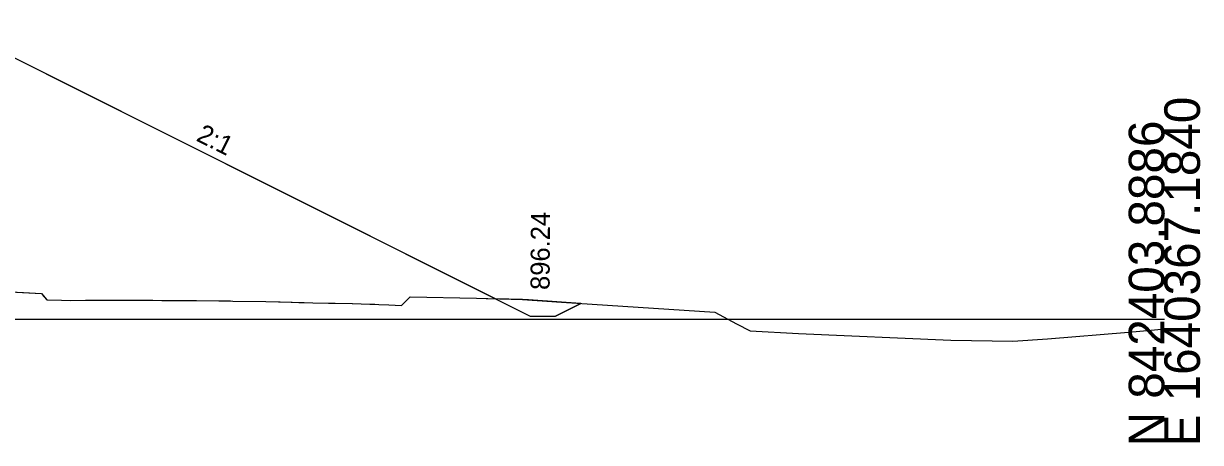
# Model space of a CAD drawing. Extents: x -26 to 1638757, y -10 to 843341.
# Drawn here: x 1260.3 to 1352.8, y 1490.3 to 1523.2 of the extents above; entities that cross this region are included whole.
import ezdxf

# ---------------------------------------------------------------- set-up
doc = ezdxf.new("R2010")
doc.units = 0
for name, color, linetype in [('Exist Cross Section Cell', 7, 'Continuous'), ('Exist XS Ground Line', 7, 'Continuous'), ('Prop CMT Slope Grass', 7, 'Continuous'), ('Prop XS DDE', 7, 'Continuous'), ('Prop XS SE Text', 7, 'Continuous'), ('Prop XS Side Slope Text', 7, 'Continuous'), ('Scratch_Level_0', 7, 'Continuous'), ('Scratch_Level_2', 7, 'Continuous'), ('Scratch_Level_3', 7, 'Continuous')]:
    doc.layers.add(name, color=color, linetype=linetype)

msp = doc.modelspace()

# ---------------------------------------------------------------- linework, layer by layer
at = {"layer": 'Exist Cross Section Cell'}
msp.add_line((1150, 1500), (1350, 1500), dxfattribs=at)
at = {"layer": 'Exist XS Ground Line'}
for points in [[(1257.864, 1502.232), (1261.7, 1502.007), (1261.875, 1501.79), (1262.103, 1501.511), (1263.28, 1501.48), (1263.993, 1501.461), (1265.156, 1501.482), (1265.721, 1501.488), (1266.927, 1501.495), (1268.445, 1501.501), (1270.439, 1501.483), (1271.168, 1501.477), (1271.724, 1501.472), (1273.892, 1501.46), (1275.651, 1501.437), (1276.088, 1501.432), (1276.57, 1501.427), (1276.74, 1501.425), (1279.339, 1501.382), (1281.317, 1501.334), (1282.063, 1501.317), (1283.041, 1501.294), (1284.786, 1501.255), (1286.114, 1501.22), (1287.51, 1501.182), (1287.909, 1501.166), (1288.222, 1501.146), (1288.999, 1501.119), (1290.002, 1501.081), (1290.419, 1501.492), (1290.682, 1501.751), (1295.913, 1501.638), (1299.528, 1501.552), (1300, 1501.518)], [(1257.865, 1502.232), (1261.7, 1502.007), (1262.103, 1501.511), (1263.28, 1501.48), (1263.993, 1501.461), (1265.156, 1501.482), (1265.721, 1501.488), (1266.927, 1501.495), (1268.445, 1501.501), (1269.047, 1501.501), (1270.439, 1501.483), (1271.168, 1501.477), (1271.723, 1501.472), (1273.892, 1501.46), (1275.651, 1501.437), (1276.088, 1501.432), (1276.741, 1501.425), (1279.339, 1501.382), (1280.456, 1501.358), (1282.358, 1501.308), (1283.042, 1501.294), (1284.26, 1501.268), (1284.786, 1501.255), (1286.161, 1501.216), (1287.51, 1501.182), (1287.909, 1501.166), (1288.222, 1501.146), (1289, 1501.119), (1290.002, 1501.081), (1290.682, 1501.751), (1295.913, 1501.638), (1299.528, 1501.552), (1302.594, 1501.328), (1314.645, 1500.56), (1316.353, 1499.624), (1317.43, 1499.085), (1321.218, 1498.875), (1333.213, 1498.343), (1338.074, 1498.264), (1340.82, 1498.442), (1347.175, 1498.97), (1348.968, 1499.137), (1350, 1499.227)]]:
    msp.add_lwpolyline(points, dxfattribs=at)
at = {"layer": 'Prop CMT Slope Grass'}
msp.add_lwpolyline([(1249.926, 1523.234), (1251.936, 1523.073), (1254.936, 1522.833), (1297.396, 1501.603)], dxfattribs=at)
at = {"layer": 'Prop XS DDE'}
for p, q in [((1297.396, 1501.603), (1300.121, 1500.24)), ((1304.119, 1501.239), (1302.121, 1500.24)), ((1300.121, 1500.24), (1302.121, 1500.24))]:
    msp.add_line(p, q, dxfattribs=at)
at = {"layer": 'Scratch_Level_2'}
for p, q in [((1299.528, 1501.552), (1297.396, 1501.603)), ((1297.396, 1501.603), (1300.121, 1500.24)), ((1304.104, 1501.231), (1302.594, 1501.328)), ((1302.121, 1500.24), (1304.104, 1501.231)), ((1300.121, 1500.24), (1302.121, 1500.24))]:
    msp.add_line(p, q, dxfattribs=at)
msp.add_lwpolyline([(1302.594, 1501.328), (1300, 1501.518), (1299.528, 1501.552)], dxfattribs=at)
at = {"layer": 'Scratch_Level_3'}
for p, q in [((1297.396, 1501.603), (1256.246, 1522.178)), ((1257.864, 1502.232), (1261.7, 1502.007)), ((1262.103, 1501.511), (1263.28, 1501.48)), ((1265.721, 1501.488), (1266.927, 1501.495)), ((1266.927, 1501.495), (1268.445, 1501.501)), ((1270.439, 1501.483), (1271.168, 1501.477)), ((1271.168, 1501.477), (1271.724, 1501.472)), ((1271.724, 1501.472), (1273.892, 1501.46)), ((1282.358, 1501.308), (1283.041, 1501.294))]:
    msp.add_line(p, q, dxfattribs=at)
for points in [[(1261.7, 1502.007), (1261.875, 1501.79), (1262.103, 1501.511)], [(1263.28, 1501.48), (1263.993, 1501.461), (1265.156, 1501.482), (1265.721, 1501.488)], [(1268.445, 1501.501), (1269.047, 1501.501), (1270.439, 1501.483)], [(1273.892, 1501.46), (1275.651, 1501.437), (1276.088, 1501.432)], [(1276.088, 1501.432), (1276.57, 1501.427), (1276.74, 1501.425), (1279.339, 1501.382)], [(1279.339, 1501.382), (1280.456, 1501.358), (1281.317, 1501.336)], [(1281.317, 1501.334), (1281.935, 1501.32), (1282.063, 1501.317), (1282.358, 1501.31)], [(1283.041, 1501.294), (1284.26, 1501.267), (1284.786, 1501.255), (1286.114, 1501.22), (1287.51, 1501.182)], [(1290.002, 1501.081), (1290.419, 1501.492), (1290.682, 1501.751), (1295.913, 1501.638), (1297.396, 1501.603)], [(1287.51, 1501.182), (1287.909, 1501.166), (1288.222, 1501.146), (1288.999, 1501.119), (1290.002, 1501.081)]]:
    msp.add_lwpolyline(points, dxfattribs=at)

# ---------------------------------------------------------------- texts
at = {"layer": 'Exist Cross Section Cell'}
for s, p in [('E 1640367.1840', (1352.8, 1490)), ('N 842403.8886', (1350, 1490))]:
    msp.add_text(s, height=2.8, rotation=90, dxfattribs=at).set_placement(p)
at = {"layer": 'Prop XS SE Text'}
msp.add_text('896.24', height=1.5, rotation=89.68642, dxfattribs=at).set_placement((1301.651, 1502.291))
at = {"layer": 'Prop XS Side Slope Text'}
msp.add_text('2:1', height=1.5, rotation=333.47149, dxfattribs=at).set_placement((1273.782, 1514.057))
at = {"layer": 'Scratch_Level_0'}
for s, p in [('Exterior Boundary', (1294.607, 1501.654)), ('RT_Slope_Fill', (1294.622, 1501.654))]:
    msp.add_text(s, height=0.01, dxfattribs=at).set_placement(p)

doc.saveas('drawing.dxf')
